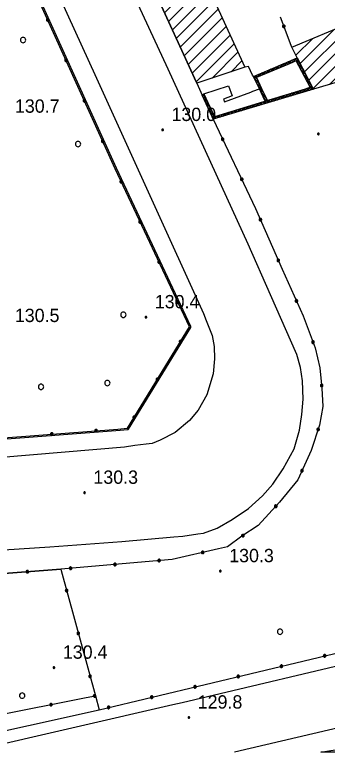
# Model space of a CAD drawing. Extents: x 513373 to 514978, y 5038576 to 5040180.
# Drawn here: x 513550.7 to 513585.9, y 5038580.1 to 5038663.1 of the extents above; entities that cross this region are included whole.
import ezdxf

# ---------------------------------------------------------------- set-up
doc = ezdxf.new("R2010")
doc.units = 0
for name, color, linetype in [('2010300', 7, 'Continuous'), ('B1211', 7, 'Continuous'), ('C1131', 7, 'Continuous'), ('C12211', 7, 'Continuous'), ('C211123', 7, 'Continuous'), ('C21195', 7, 'Continuous'), ('C2911', 7, 'Continuous'), ('C4114', 7, 'Continuous'), ('CAMP_C21195', 7, 'Continuous'), ('CAMP_C4114', 7, 'Continuous'), ('Default', 7, 'Continuous'), ('F12107', 7, 'Continuous'), ('G4315', 7, 'Continuous'), ('TOP920', 7, 'Continuous')]:
    doc.layers.add(name, color=color, linetype=linetype)

# ---------------------------------------------------------------- blocks, each defined once
blk = doc.blocks.new('CAMP_8B703627')
at = {"layer": 'CAMP_C21195'}
for p, q in [((-7.02, 8.536), (-3.937, 11.62)), ((-6.576, 7.566), (-2.299, 11.843)), ((-6.132, 6.596), (-1.855, 10.873)), ((-7.464, 9.506), (-6.62, 10.351)), ((-5.688, 5.626), (-1.411, 9.903)), ((-5.244, 4.656), (-0.967, 8.933)), ((-4.799, 3.686), (-0.523, 7.963)), ((-4.355, 2.716), (-0.079, 6.992)), ((-3.911, 1.746), (0.366, 6.022)), ((-3.467, 0.776), (0.81, 5.052)), ((-3.023, -0.194), (1.254, 4.082)), ((-2.579, -1.165), (1.698, 3.112)), ((-2.135, -2.135), (2.142, 2.142)), ((-1.69, -3.105), (2.586, 1.172)), ((-1.246, -4.075), (3.03, 0.202)), ((-0.802, -5.045), (3.475, -0.768)), ((-0.358, -6.015), (3.919, -1.738)), ((0.086, -6.985), (4.363, -2.708)), ((0.53, -7.955), (4.807, -3.678)), ((0.974, -8.925), (5.251, -4.648)), ((1.419, -9.895), (5.695, -5.618)), ((1.863, -10.865), (6.14, -6.588)), ((2.307, -11.835), (6.584, -7.558)), ((4.135, -11.422), (7.028, -8.529)), ((6.248, -10.723), (7.472, -9.499))]:
    blk.add_line(p, q, dxfattribs=at)
blk = doc.blocks.new('CAMP_1860F2A3')
at = {"layer": 'CAMP_C21195'}
for p, q in [((-3.757, -1.636), (1.994, 4.115)), ((-3.276, -2.569), (2.71, 3.417)), ((-4.239, -0.703), (-0.411, 3.125)), ((-4.72, 0.23), (-2.816, 2.134)), ((-2.795, -3.502), (3.034, 2.327)), ((-0.937, -3.059), (3.358, 1.237)), ((1.076, -2.459), (3.682, 0.146)), ((3.09, -1.86), (4.006, -0.944))]:
    blk.add_line(p, q, dxfattribs=at)
blk = doc.blocks.new('CAMP_59053F43')
at = {"layer": 'CAMP_C4114'}
for p, q in [((0.021, 0.251), (-0.424, 0.696)), ((-0.355, 0.496), (-0.177, 0.675)), ((-0.268, 0.301), (-0.087, 0.482)), ((0.269, -0.28), (-0.231, 0.22)), ((-0.18, 0.107), (0.003, 0.289)), ((-0.092, -0.088), (0.093, 0.096)), ((-0.004, -0.283), (0.183, -0.096)), ((0.353, -0.647), (0.002, -0.296)), ((0.084, -0.478), (0.273, -0.289)), ((0.172, -0.673), (0.363, -0.482))]:
    blk.add_line(p, q, dxfattribs=at)
blk = doc.blocks.new('CAMP_144D1B41')
at = {"layer": 'CAMP_C4114'}
for p, q in [((2.565, 2.988), (3.072, 3.495)), ((2.993, 3.166), (2.786, 3.374)), ((3.193, 3.249), (2.984, 3.458)), ((3.049, 3.189), (3.563, 3.703)), ((3.393, 3.332), (3.183, 3.542)), ((4.017, 2.99), (3.382, 3.626)), ((3.521, 3.378), (3.716, 3.574)), ((3.716, 3.575), (3.58, 3.71)), ((3.619, 3.193), (3.813, 3.387)), ((0.629, 2.183), (1.11, 2.664)), ((0.995, 2.335), (0.799, 2.532)), ((1.195, 2.418), (0.997, 2.616)), ((1.113, 2.384), (1.6, 2.872)), ((1.395, 2.501), (1.196, 2.7)), ((1.595, 2.584), (1.395, 2.785)), ((1.795, 2.668), (1.593, 2.869)), ((1.597, 2.585), (2.091, 3.079)), ((1.994, 2.751), (1.792, 2.953)), ((2.194, 2.834), (1.991, 3.037)), ((2.081, 2.787), (2.581, 3.287)), ((2.394, 2.917), (2.19, 3.121)), ((2.594, 3), (2.388, 3.205)), ((2.794, 3.083), (2.587, 3.289)), ((3.717, 3.008), (3.909, 3.2)), ((4.319, 2.406), (3.718, 3.007)), ((3.815, 2.824), (4.005, 3.014)), ((3.913, 2.639), (4.102, 2.827)), ((4.011, 2.454), (4.198, 2.641)), ((-1.224, 1.461), (-0.853, 1.833)), ((-0.914, 1.416), (-1.188, 1.691)), ((-0.803, 1.588), (-0.99, 1.775)), ((-0.823, 1.579), (-0.362, 2.04)), ((-0.603, 1.671), (-0.791, 1.859)), ((-0.403, 1.754), (-0.592, 1.943)), ((-0.203, 1.837), (-0.394, 2.027)), ((-0.339, 1.781), (0.128, 2.248)), ((-0.004, 1.92), (-0.195, 2.111)), ((0.196, 2.003), (0.004, 2.196)), ((0.145, 1.982), (0.619, 2.456)), ((0.396, 2.086), (0.203, 2.28)), ((0.596, 2.169), (0.401, 2.364)), ((0.796, 2.252), (0.6, 2.448)), ((4.62, 1.822), (4.036, 2.406)), ((4.109, 2.269), (4.294, 2.454)), ((4.206, 2.084), (4.39, 2.268)), ((4.304, 1.899), (4.487, 2.081)), ((4.922, 1.237), (4.353, 1.806)), ((4.402, 1.714), (4.583, 1.894)), ((4.5, 1.529), (4.679, 1.708)), ((-0.656, 0.876), (-1.207, 1.426)), ((-1.13, 1.273), (-0.937, 1.466)), ((-1.036, 1.084), (-0.846, 1.274)), ((-0.941, 0.896), (-0.755, 1.082)), ((-0.399, 0.336), (-0.924, 0.86)), ((-0.847, 0.707), (-0.663, 0.891)), ((4.598, 1.344), (4.775, 1.521)), ((5.223, 0.653), (4.671, 1.205)), ((4.696, 1.159), (4.872, 1.335)), ((4.794, 0.974), (4.968, 1.148)), ((4.892, 0.789), (5.064, 0.961)), ((-0.753, 0.519), (-0.572, 0.699)), ((-0.658, 0.33), (-0.481, 0.508)), ((-0.593, 0.246), (-0.64, 0.294)), ((-0.415, 0.291), (-0.39, 0.316)), ((3.401, -0.419), (3.854, 0.035)), ((3.803, -0.299), (4.263, 0.16)), ((4.106, -0.209), (3.86, 0.036)), ((4.324, -0.144), (4.076, 0.103)), ((4.206, -0.179), (4.672, 0.286)), ((4.542, -0.08), (4.293, 0.17)), ((4.76, -0.015), (4.509, 0.236)), ((4.609, -0.06), (5.081, 0.412)), ((4.978, 0.05), (4.725, 0.303)), ((5.196, 0.115), (4.941, 0.369)), ((4.989, 0.604), (5.16, 0.775)), ((5.414, 0.18), (4.989, 0.604)), ((5.011, 0.06), (5.353, 0.402)), ((5.087, 0.419), (5.257, 0.588)), ((5.414, 0.18), (5.449, 0.215)), ((-6.659, -0.758), (-7.013, -0.404)), ((-6.994, -0.632), (-6.804, -0.442)), ((-6.42, -1.28), (-6.932, -0.768)), ((-6.906, -0.826), (-6.715, -0.636)), ((0.984, -1.139), (1.402, -0.721)), ((1.49, -0.988), (1.265, -0.763)), ((1.387, -1.019), (1.811, -0.595)), ((1.708, -0.923), (1.482, -0.696)), ((1.926, -0.858), (1.698, -0.63)), ((1.79, -0.899), (2.219, -0.469)), ((2.144, -0.793), (1.914, -0.563)), ((2.362, -0.728), (2.13, -0.497)), ((2.192, -0.779), (2.628, -0.343)), ((2.58, -0.664), (2.347, -0.43)), ((2.798, -0.599), (2.563, -0.363)), ((2.595, -0.659), (3.037, -0.217)), ((3.016, -0.534), (2.779, -0.297)), ((3.234, -0.469), (2.995, -0.23)), ((2.998, -0.539), (3.446, -0.091)), ((3.452, -0.404), (3.211, -0.164)), ((3.67, -0.339), (3.428, -0.097)), ((3.888, -0.274), (3.644, -0.03)), ((-6.817, -1.02), (-6.626, -0.83)), ((-6.728, -1.214), (-6.538, -1.024)), ((-6.182, -1.801), (-6.693, -1.29)), ((-6.639, -1.408), (-6.449, -1.218)), ((-6.55, -1.602), (-6.36, -1.412)), ((-6.461, -1.796), (-6.271, -1.606)), ((-1.835, -1.978), (-1.46, -1.603)), ((-1.343, -1.831), (-1.546, -1.629)), ((-1.432, -1.858), (-1.051, -1.477)), ((-1.125, -1.767), (-1.329, -1.562)), ((-0.907, -1.702), (-1.113, -1.496)), ((-1.029, -1.738), (-0.642, -1.351)), ((-0.689, -1.637), (-0.897, -1.429)), ((-0.471, -1.572), (-0.681, -1.363)), ((-0.627, -1.618), (-0.233, -1.225)), ((-0.253, -1.507), (-0.464, -1.296)), ((-0.035, -1.442), (-0.248, -1.229)), ((-0.224, -1.498), (0.176, -1.099)), ((0.183, -1.377), (-0.032, -1.163)), ((0.179, -1.378), (0.584, -0.973)), ((0.401, -1.312), (0.184, -1.096)), ((0.618, -1.247), (0.4, -1.029)), ((0.581, -1.258), (0.993, -0.847)), ((0.836, -1.183), (0.617, -0.963)), ((1.054, -1.118), (0.833, -0.896)), ((1.272, -1.053), (1.049, -0.83)), ((-5.943, -2.323), (-6.454, -1.812)), ((-6.372, -1.99), (-6.182, -1.8)), ((-6.284, -2.184), (-6.093, -1.994)), ((-5.704, -2.845), (-6.215, -2.334)), ((-6.195, -2.378), (-6.005, -2.188)), ((-6.106, -2.572), (-5.916, -2.382)), ((-4.654, -2.817), (-4.321, -2.484)), ((-4.251, -2.697), (-3.912, -2.358)), ((-3.959, -2.61), (-4.14, -2.428)), ((-3.741, -2.545), (-3.924, -2.362)), ((-3.849, -2.577), (-3.503, -2.232)), ((-3.523, -2.48), (-3.708, -2.295)), ((-3.305, -2.415), (-3.492, -2.229)), ((-3.446, -2.457), (-3.095, -2.106)), ((-3.087, -2.351), (-3.275, -2.162)), ((-2.869, -2.286), (-3.059, -2.095)), ((-3.043, -2.338), (-2.686, -1.98)), ((-2.651, -2.221), (-2.843, -2.029)), ((-2.64, -2.218), (-2.277, -1.854)), ((-2.433, -2.156), (-2.627, -1.962)), ((-2.215, -2.091), (-2.41, -1.895)), ((-2.238, -2.098), (-1.868, -1.729)), ((-1.997, -2.026), (-2.194, -1.829)), ((-1.779, -1.961), (-1.978, -1.762)), ((-1.561, -1.896), (-1.762, -1.696)), ((-6.017, -2.766), (-5.827, -2.576)), ((-5.702, -3.129), (-5.976, -2.856)), ((-5.928, -2.96), (-5.738, -2.77)), ((-5.839, -3.154), (-5.547, -2.862)), ((-5.484, -3.064), (-5.654, -2.895)), ((-5.46, -3.057), (-5.138, -2.736)), ((-5.266, -2.999), (-5.438, -2.828)), ((-5.048, -2.934), (-5.222, -2.761)), ((-5.057, -2.937), (-4.73, -2.61)), ((-4.83, -2.87), (-5.005, -2.695)), ((-4.613, -2.805), (-4.789, -2.628)), ((-4.395, -2.74), (-4.573, -2.562)), ((-4.177, -2.675), (-4.357, -2.495))]:
    blk.add_line(p, q, dxfattribs=at)
blk = doc.blocks.new('03080200')
at = {"layer": 'Default'}
for p, q in [((-0.139, 0.046), (-0.146, 0)), ((-0.146, 0), (-0.139, -0.046)), ((-0.118, 0.086), (-0.139, 0.046)), ((-0.086, 0.118), (-0.118, 0.086)), ((-0.046, 0.139), (-0.086, 0.118)), ((0, 0.146), (-0.046, 0.139)), ((-0.042, 0.014), (-0.045, 0)), ((-0.045, 0), (-0.042, -0.014)), ((-0.036, 0.026), (-0.042, 0.014)), ((-0.026, 0.036), (-0.036, 0.026)), ((-0.014, 0.042), (-0.026, 0.036)), ((0, 0.045), (-0.014, 0.042)), ((0.046, 0.139), (0, 0.146)), ((0.014, 0.042), (0, 0.045)), ((0.026, 0.036), (0.014, 0.042)), ((0.036, 0.026), (0.026, 0.036)), ((0.042, 0.014), (0.036, 0.026)), ((0.045, 0), (0.042, 0.014)), ((0.042, -0.014), (0.045, 0)), ((0.086, 0.118), (0.046, 0.139)), ((0.118, 0.086), (0.086, 0.118)), ((0.139, 0.046), (0.118, 0.086)), ((0.146, 0), (0.139, 0.046)), ((0.139, -0.046), (0.146, 0)), ((-0.139, -0.046), (-0.118, -0.086)), ((-0.118, -0.086), (-0.086, -0.118)), ((-0.086, -0.118), (-0.046, -0.139)), ((-0.046, -0.139), (0, -0.146)), ((-0.042, -0.014), (-0.036, -0.026)), ((-0.036, -0.026), (-0.026, -0.036)), ((-0.026, -0.036), (-0.014, -0.042)), ((-0.014, -0.042), (0, -0.045)), ((0, -0.045), (0.014, -0.042)), ((0, -0.146), (0.046, -0.139)), ((0.014, -0.042), (0.026, -0.036)), ((0.026, -0.036), (0.036, -0.026)), ((0.036, -0.026), (0.042, -0.014)), ((0.046, -0.139), (0.086, -0.118)), ((0.086, -0.118), (0.118, -0.086)), ((0.118, -0.086), (0.139, -0.046))]:
    blk.add_line(p, q, dxfattribs=at)
blk = doc.blocks.new('08020400')
at = {"layer": 'Default'}
for p, q in [((-0.086, 0.028), (-0.09, 0)), ((-0.09, 0), (-0.086, -0.028)), ((-0.073, 0.053), (-0.086, 0.028)), ((-0.053, 0.073), (-0.073, 0.053)), ((-0.028, 0.086), (-0.053, 0.073)), ((0, 0.09), (-0.028, 0.086)), ((0.028, 0.086), (0, 0.09)), ((0.053, 0.073), (0.028, 0.086)), ((0.073, 0.053), (0.053, 0.073)), ((0.086, 0.028), (0.073, 0.053)), ((0.09, 0), (0.086, 0.028)), ((0.086, -0.028), (0.09, 0)), ((-0.086, -0.028), (-0.073, -0.053)), ((-0.073, -0.053), (-0.053, -0.073)), ((-0.053, -0.073), (-0.028, -0.086)), ((-0.028, -0.086), (0, -0.09)), ((0, -0.09), (0.028, -0.086)), ((0.028, -0.086), (0.053, -0.073)), ((0.053, -0.073), (0.073, -0.053)), ((0.073, -0.053), (0.086, -0.028))]:
    blk.add_line(p, q, dxfattribs=at)
blk = doc.blocks.new('05010100')
at = {"layer": 'Default'}
for p, q in [((-0.143, 0.046), (-0.15, 0)), ((-0.15, 0), (-0.143, -0.046)), ((-0.121, 0.088), (-0.143, 0.046)), ((-0.088, 0.121), (-0.121, 0.088)), ((-0.046, 0.143), (-0.088, 0.121)), ((0, 0.15), (-0.046, 0.143)), ((0.046, 0.143), (0, 0.15)), ((0.088, 0.121), (0.046, 0.143)), ((0.121, 0.088), (0.088, 0.121)), ((0.143, 0.046), (0.121, 0.088)), ((0.15, 0), (0.143, 0.046)), ((0.143, -0.046), (0.15, 0)), ((-0.143, -0.046), (-0.121, -0.088)), ((-0.121, -0.088), (-0.088, -0.121)), ((-0.088, -0.121), (-0.046, -0.143)), ((-0.046, -0.143), (0, -0.15)), ((0, -0.15), (0.046, -0.143)), ((0.046, -0.143), (0.088, -0.121)), ((0.088, -0.121), (0.121, -0.088)), ((0.121, -0.088), (0.143, -0.046))]:
    blk.add_line(p, q, dxfattribs=at)
blk = doc.blocks.new('A$C3704598A')
at = {"layer": '2010300'}
for points in [[(234.601, -792.459), (233.662, -792.679), (233.579, -792.699), (226.471, -794.366), (202.43, -800.003)], [(165.65, -800.002), (186.154, -795.446), (186.667, -795.332), (187.178, -795.219)]]:
    blk.add_lwpolyline(points, dxfattribs=at)
at = {"layer": 'B1211'}
for points in [[(188.144, -702.831), (198.118, -724.615), (198.159, -724.704), (198.77, -726.038), (199.895, -728.496), (199.987, -728.696), (200.015, -728.756), (204.775, -738.796), (207.776, -745.627), (210.157, -750.905), (211.489, -754.479), (212.011, -756.741), (212.257, -759.032), (212.344, -761.076), (211.996, -763.208), (211.039, -766.035), (209.56, -769.341), (207.472, -771.864), (205.08, -774.474), (203.253, -775.692), (201.643, -776.867), (200.621, -777.101), (195.379, -778.302), (182.854, -779.395), (110.289, -784.942)], [(148.809, -779.036), (181.633, -776.874), (189.73, -776.302), (195.581, -775.77), (196.614, -775.676), (198.296, -775.441), (198.917, -775.355), (200.454, -774.784), (202.158, -773.813), (203.973, -772.569), (205.554, -771.141), (206.713, -769.837), (207.894, -768.114), (209.116, -765.862), (209.716, -763.77), (209.986, -761.984), (210.146, -760.253), (210.071, -758.21), (209.828, -756.694), (209.438, -755.249), (206.452, -748.51), (203.939, -742.84), (194.962, -723.144), (187.936, -707.965)], [(138.496, -767.667), (189.536, -763.755), (190.396, -763.689), (190.436, -763.676), (190.461, -763.661), (190.489, -763.632), (197.481, -752.214), (197.493, -752.184), (197.499, -752.151), (197.498, -752.122), (197.49, -752.091), (189.117, -734.281), (180.333, -714.883), (179.442, -712.916), (176.443, -705.942)], [(177.382, -705.641), (178.147, -705.709), (178.598, -705.932), (179.608, -708.147), (186.889, -724.147), (193.069, -737.752), (198.911, -750.632), (199.214, -751.398), (199.885, -753.097), (200.128, -754.346), (200.171, -755.739), (200.013, -757.4), (199.307, -759.798), (198.336, -761.489), (197.35, -762.656), (195.749, -764.017), (194.061, -764.871), (193.136, -765.243), (192.488, -765.328), (191.203, -765.498), (190.042, -765.652), (176.206, -766.841)]]:
    blk.add_lwpolyline(points, dxfattribs=at)
blk.add_lwpolyline([(239.733, -784.162), (238.193, -784.525), (218.713, -789.182), (196.51, -794.439), (195.488, -794.673), (173.196, -799.794), (172.259, -800.002), (165.65, -800.002), (186.154, -795.446), (186.667, -795.332), (187.178, -795.219), (234.926, -783.811), (239.656, -782.696), (240.683, -782.453)], close=True, dxfattribs=at)
at = {"layer": 'C1131'}
for points in [[(203.574, -722.913), (198.159, -724.704), (198.118, -724.615), (188.144, -702.831), (192.339, -700.847), (193.269, -700.407)], [(218.234, -723.332), (217.669, -723.5), (211.307, -725.394), (211.277, -725.335), (209.482, -721.855), (208.857, -720.644), (215.526, -717.896), (215.891, -717.746), (216.501, -717.495)], [(227.023, -797.613), (227.423, -800.003), (212.119, -800.003), (227.013, -797.548)]]:
    blk.add_lwpolyline(points, close=True, dxfattribs=at)
at = {"layer": 'C12211'}
blk.add_lwpolyline([(239.195, -792.051), (240.555, -800.003), (212.119, -800.003), (227.013, -797.548), (234.229, -796.359), (235.262, -796.188), (234.939, -794.366), (234.611, -792.516), (234.601, -792.459), (238.1, -791.855), (238.729, -791.747), (239.131, -791.677)], close=True, dxfattribs=at)
at = {"layer": 'C211123'}
blk.add_lwpolyline([(201.168, -726.508), (201.276, -726.802), (204.265, -725.703), (204.488, -725.621), (205.234, -725.347), (205.829, -726.667), (205.861, -726.737), (205.695, -726.788), (200.17, -728.49), (200.138, -728.421), (198.98, -725.891), (201.734, -725.024), (202.147, -726.148)], close=True, dxfattribs=at)
at = {"layer": 'C21195'}
for points in [[(203.574, -722.913), (198.159, -724.704), (198.118, -724.615), (188.144, -702.831), (192.339, -700.847), (193.269, -700.407)], [(218.234, -723.332), (217.669, -723.5), (211.307, -725.394), (211.277, -725.335), (209.482, -721.855), (208.857, -720.644), (215.526, -717.896), (215.891, -717.746), (216.501, -717.495)]]:
    blk.add_lwpolyline(points, close=True, dxfattribs=at)
at = {"layer": 'C2911'}
for points in [[(129.493, -768.231), (138.486, -767.517), (158.144, -766.013), (189.264, -763.627), (189.631, -763.599), (190.369, -763.543), (197.35, -752.142), (188.981, -734.343), (179.304, -712.974), (176.303, -705.995)], [(208.857, -720.644), (208.796, -720.484), (207.577, -717.268)], [(204.535, -723.95), (204.454, -723.787), (203.983, -722.828), (203.574, -722.913)], [(200.015, -728.756), (204.775, -738.796), (207.776, -745.627), (210.157, -750.905), (211.489, -754.479), (212.011, -756.741), (212.257, -759.032), (212.344, -761.076), (211.996, -763.208), (211.039, -766.035), (209.56, -769.341), (207.472, -771.864), (205.08, -774.474), (203.253, -775.692), (201.643, -776.867), (200.621, -777.101), (195.379, -778.302), (182.854, -779.395)], [(182.854, -779.395), (182.893, -779.538), (186.751, -793.656), (187.176, -795.211), (187.178, -795.219), (234.926, -783.811), (234.924, -783.805), (233.651, -778.34)], [(71.944, -788.357), (110.289, -784.942), (182.854, -779.395)], [(154.78, -800.002), (185.721, -793.86), (186.751, -793.656)]]:
    blk.add_lwpolyline(points, dxfattribs=at)
at = {"layer": 'C4114'}
for points in [[(211.307, -725.394), (200.015, -728.756), (199.987, -728.696), (199.895, -728.496), (198.77, -726.038), (198.98, -725.891), (200.138, -728.421), (200.17, -728.49), (205.695, -726.788), (205.861, -726.737), (206.106, -726.661), (206.188, -726.636), (210.17, -725.409), (210.937, -725.173), (209.366, -722.204), (208.667, -722.494), (208.425, -722.595), (204.884, -724.067), (205.466, -725.289), (205.234, -725.347), (204.565, -724.011), (204.535, -723.95), (208.542, -722.253), (209.482, -721.855), (211.277, -725.335)], [(206.106, -726.661), (205.861, -726.737), (205.829, -726.667), (205.234, -725.347), (205.466, -725.289), (206.074, -726.592)]]:
    blk.add_lwpolyline(points, close=True, dxfattribs=at)
at = {"layer": 'C2911'}
for p, rotation in [((181.388, -717.575), 114.36487038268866), ((207.97, -718.306), 110.76323227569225), ((183.45, -722.13), 114.36487038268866), ((185.513, -726.684), 114.36487038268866), ((187.576, -731.239), 114.36487038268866), ((201.086, -731.015), -64.63035431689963), ((203.228, -735.533), -64.63035431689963), ((189.659, -735.784), 115.18181093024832), ((191.787, -740.309), 115.18181093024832), ((205.334, -740.067), -66.28402516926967), ((207.345, -744.645), -66.28402516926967), ((193.914, -744.834), 115.18181093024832), ((196.042, -749.359), 115.18181093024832), ((209.391, -749.207), -65.71988578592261), ((196.345, -753.783), 58.51960815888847), ((211.253, -753.844), -69.56055033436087), ((193.734, -758.047), 58.51960815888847), ((212.225, -758.731), -83.87175058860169), ((191.123, -762.311), 58.51960815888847), ((211.838, -763.673), -108.70249336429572), ((181.838, -764.197), 4.383950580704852), ((186.824, -763.814), 4.383950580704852), ((210.015, -768.323), -114.10266271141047), ((207.06, -772.314), -132.50568571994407), ((203.358, -775.622), -146.31041086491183), ((198.835, -777.51), -167.09801961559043), ((193.93, -778.428), -175.01375275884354), ((183.968, -779.297), -175.01375275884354), ((188.949, -778.863), -175.01375275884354), ((179.092, -779.682), 4.371974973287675), ((183.513, -781.806), -74.71713242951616), ((184.831, -786.629), -74.71713242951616), ((212.559, -789.155), 13.436390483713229), ((207.696, -790.317), 13.436390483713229), ((186.149, -791.452), -74.71713242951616), ((202.833, -791.478), 13.436390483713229), ((197.97, -792.64), 13.436390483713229), ((186.658, -793.674), 11.22794415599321), ((193.107, -793.802), 13.436390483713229), ((181.754, -794.648), 11.227944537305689), ((188.244, -794.964), 13.436390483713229)]:
    blk.add_blockref('03080200', p, dxfattribs=dict(at, rotation=rotation))
at = {"layer": 'CAMP_C21195'}
for name, p in [('CAMP_8B703627', (195.776, -712.703)), ('CAMP_1860F2A3', (214.053, -721.797))]:
    blk.add_blockref(name, p, dxfattribs=at)
at = {"layer": 'CAMP_C4114'}
for name, p in [('CAMP_144D1B41', (205.847, -725.588)), ('CAMP_59053F43', (205.677, -726.038))]:
    blk.add_blockref(name, p, dxfattribs=at)
at = {"layer": 'F12107'}
for p in [(194.321, -729.965), (211.856, -730.422), (192.442, -751.046), (185.533, -770.795), (200.819, -779.615), (182.091, -790.479), (197.278, -796.09)]:
    blk.add_blockref('08020400', p, dxfattribs=at)
at = {"layer": 'G4315', "xscale": 2, "yscale": 2}
for p in [(178.616, -719.856), (184.806, -731.554), (189.904, -750.773), (180.63, -758.878), (188.109, -758.451), (207.538, -786.44), (178.508, -793.622)]:
    blk.add_blockref('05010100', p, dxfattribs=at)
at = {"layer": 'TOP920'}
for s, p in [('130.7', (177.696, -728.032)), ('130.0', (195.321, -728.965)), ('130.4', (193.442, -750.046)), ('130.5', (177.687, -751.59)), ('130.3', (186.533, -769.795)), ('130.3', (201.819, -778.615)), ('130.4', (183.091, -789.479)), ('129.8', (198.278, -795.09))]:
    blk.add_text(s, height=1.5, dxfattribs=at).set_placement(p)

msp = doc.modelspace()

# ---------------------------------------------------------------- block references
at = {"layer": 'Default'}
msp.add_blockref('A$C3704598A', (513373.046, 5039380.14), dxfattribs=at)

doc.saveas('drawing.dxf')
